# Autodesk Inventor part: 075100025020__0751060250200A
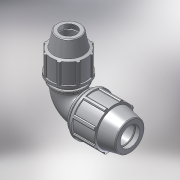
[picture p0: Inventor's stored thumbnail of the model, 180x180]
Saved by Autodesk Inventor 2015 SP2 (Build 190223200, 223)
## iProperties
Created: 2017-02
Part Number: 075100025020__0751060250200A
Material: PVC-Piping
Description: PLASSON REDUCING ELBOW 25-20
Document SubType Name: Modeling
Designer: KIM
Mass: 92.6774 g
Surface Area: 199.44 cm^2
Volume: 66.1981 cm^3
Density: 1.4 g/cm^3
Appearance: Smooth - White
Author: KIM
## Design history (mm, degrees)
derived "07510.ipt"
feature "Solid1::07510.ipt"
tag "TaggingFeature1"
body "Solid1"
other parameters: "d2" = 25, "d4" = 6.58333, "d5" = 19.75, "d7" = 54, "d9" = 11.28571, "d11" = 2.63333, "d13" = 120 deg, "d14" = 37.5, "d15" = 12 deg, "d16" = 46.98, "d18" = 1.25, "d19" = 35 deg, "d20" = 17.5 deg, "d21" = 50.22, "d23" = 0, "d25" = 360 deg, "d27" = 1.08, "d33" = 0.5, "d42" = 31.6, "d43" = 1.62, "d46" = 0.75, "d51" = 79, "d63" = 58, "d67" = 40.5, "d77" = 48, "d78" = 12 deg, "d79" = 79, "d80" = 120 deg, "d82" = 6.25, "d84" = 57, "d85" = 36, "d86" = 41.76, "d87" = 2.5, "d88" = 0.5, "d89" = 18.75, "d92" = 19.2, "d93" = 0, "d94" = 0, "d95" = 2.7, "d96" = 0.52667, "d97" = 2.7, "d98" = 44.64, "d99" = 35 deg, "d100" = 17.5 deg, "d102" = 0, "d103" = 0.96, "d107" = 360 deg, "d109" = 0.6, "d112" = 1, "d113" = 3.2, "d114" = 0, "d115" = 3.2, "d116" = 0, "d_" = 25, "E_" = 54, "A_" = 79, "l_" = 58, "E_1" = 48, "l_1" = 57, "A_1" = 75
